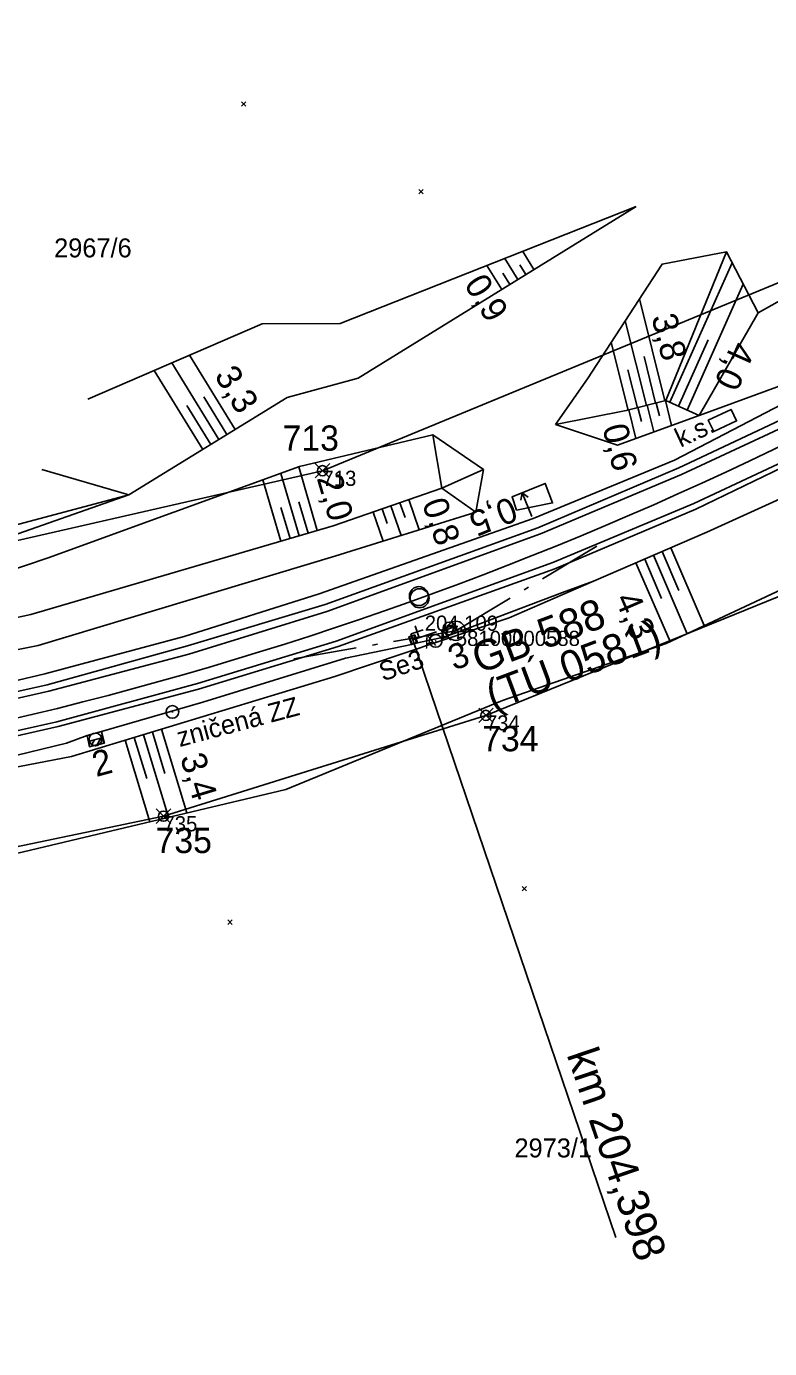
# Model space of a CAD drawing. Extents: x -800194 to -799078, y -1007177 to -1006597.
# Drawn here: x -799583.1 to -799524.3, y -1007037.9 to -1006933.3 of the extents above; entities that cross this region are included whole.
import ezdxf

# ---------------------------------------------------------------- set-up
doc = ezdxf.new("R2010")
doc.units = 0
for name, color, linetype in [('02_Osa_koleje', 7, 'Continuous'), ('_Vrstva 7 - Přesunutá', 7, 'Continuous'), ('Obvod stavby', 7, 'Continuous'), ('Vrstva 11', 7, 'Continuous'), ('Vrstva 12', 7, 'Continuous'), ('Vrstva 13', 7, 'Continuous'), ('Vrstva 25', 7, 'Continuous'), ('Vrstva 4', 7, 'Continuous'), ('Vrstva 48', 7, 'Continuous'), ('Vrstva 49', 7, 'Continuous'), ('Vrstva 50', 7, 'Continuous'), ('Vrstva 53', 7, 'Continuous'), ('Vrstva 55', 7, 'Continuous'), ('Vrstva 57', 7, 'Continuous'), ('Vrstva 6', 7, 'Continuous'), ('Vrstva 60', 7, 'Continuous'), ('Vrstva 61', 7, 'Continuous'), ('Vrstva 63', 7, 'Continuous'), ('Vrstva 7', 7, 'Continuous')]:
    doc.layers.add(name, color=color, linetype=linetype)

msp = doc.modelspace()

# ---------------------------------------------------------------- linework, layer by layer
at = {"layer": '02_Osa_koleje'}
msp.add_arc((-799651.02, -1006703.89), 292, 255.6249, 308.2052, dxfattribs=at)
at = {"layer": '_Vrstva 7 - Přesunutá'}
msp.add_circle((-799551.96, -1006978.57), 0.75, dxfattribs=at)
at = {"layer": 'Obvod stavby'}
for p, q in [((-799560.21, -1006969.05), (-799559.07, -1006967.91)), ((-799560.21, -1006967.91), (-799559.07, -1006969.05)), ((-799547.28, -1006988.4), (-799546.14, -1006987.26)), ((-799547.28, -1006987.26), (-799546.14, -1006988.4)), ((-799572.79, -1006996.37), (-799571.65, -1006995.23)), ((-799572.79, -1006995.23), (-799571.65, -1006996.37))]:
    msp.add_line(p, q, dxfattribs=at)
for points in [[(-799683.81, -1006990.52), (-799664.23, -1006992.09), (-799644.23, -1006992.31), (-799624.62, -1006991.18), (-799605.02, -1006988.7), (-799601.63, -1006988.13), (-799603.07, -1006978.39), (-799559.64, -1006968.48), (-799519.68, -1006952.01)], [(-799521.98, -1006977.8), (-799546.71, -1006987.83), (-799572.22, -1006995.8), (-799583.97, -1006998.26), (-799599.63, -1007001.65), (-799600.6, -1006995.06), (-799604.02, -1006995.63), (-799623.98, -1006998.15), (-799644.19, -1006999.31), (-799664.43, -1006999.09), (-799684.6, -1006997.48)]]:
    msp.add_lwpolyline(points, dxfattribs=at)
for centre in [(-799559.64, -1006968.48), (-799546.71, -1006987.83), (-799572.22, -1006995.8)]:
    msp.add_circle(centre, 0.4, dxfattribs=at)
at = {"layer": 'Vrstva 11'}
for p, q in [((-799549.13, -1006980.79), (-799550.08, -1006981.14)), ((-799549.87, -1006981.38), (-799549.69, -1006981)), ((-799549.49, -1006981.45), (-799549.2, -1006980.81)), ((-799577.11, -1006989.6), (-799578.08, -1006989.86)), ((-799577.53, -1006990.23), (-799577.18, -1006989.62)), ((-799577.9, -1006990.13), (-799577.69, -1006989.76))]:
    msp.add_line(p, q, dxfattribs=at)
for centre in [(-799549.6, -1006980.96), (-799577.6, -1006989.73)]:
    msp.add_circle(centre, 0.503, dxfattribs=at)
for centre, start, end in [((-799549.6, -1006980.96), 200.5311, 20.5311), ((-799577.6, -1006989.73), 194.9449, 14.9449)]:
    msp.add_arc(centre, 0.503, start, end, dxfattribs=at)
at = {"layer": 'Vrstva 12'}
for p, q in [((-799552.8, -1006981.61), (-799552.75, -1006981.62)), ((-799552.57, -1006982.18), (-799552.61, -1006982.23)), ((-799552.38, -1006981.51), (-799552.33, -1006981.46)), ((-799552.2, -1006982.07), (-799552.13, -1006982.09))]:
    msp.add_line(p, q, dxfattribs=at)
for points in [[(-799550.23, -1006981.08), (-799550.03, -1006981.64), (-799548.93, -1006981.25), (-799549.17, -1006980.59), (-799550.23, -1006981.08)], [(-799550.23, -1006981.08), (-799550.03, -1006981.64), (-799548.93, -1006981.25), (-799549.17, -1006980.59)], [(-799548.93, -1006981.25), (-799548.93, -1006981.25)], [(-799552.33, -1006981.46), (-799552.8, -1006981.61), (-799552.61, -1006982.23), (-799552.13, -1006982.09), (-799552.33, -1006981.46)], [(-799552.75, -1006981.62), (-799552.38, -1006981.51), (-799552.2, -1006982.07), (-799552.57, -1006982.18), (-799552.75, -1006981.62)], [(-799550.03, -1006981.64), (-799550.03, -1006981.64)], [(-799577.13, -1006989.11), (-799576.89, -1006990.02), (-799578.08, -1006990.31), (-799578.26, -1006989.41)], [(-799576.94, -1006990.02), (-799578.06, -1006990.29), (-799578.26, -1006989.41), (-799577.13, -1006989.11), (-799576.94, -1006990.02)], [(-799578.06, -1006990.29), (-799578.08, -1006990.31)], [(-799576.94, -1006990.02), (-799576.89, -1006990.02)]]:
    msp.add_lwpolyline(points, dxfattribs=at)
at = {"layer": 'Vrstva 13'}
for p, q in [((-799542.02, -1006969.49), (-799544.64, -1006970.55)), ((-799543.09, -1006972.09), (-799543.84, -1006970.23))]:
    msp.add_line(p, q, dxfattribs=at)
for points in [[(-799544.28, -1006971.59), (-799541.43, -1006971.03), (-799542.01, -1006969.49), (-799544.64, -1006970.55), (-799544.28, -1006971.59)], [(-799542.01, -1006969.49), (-799542.02, -1006969.49), (-799541.43, -1006971.03)], [(-799544.28, -1006971.59), (-799544.64, -1006970.55), (-799544.64, -1006970.55)], [(-799543.38, -1006970.58), (-799543.84, -1006970.23), (-799543.94, -1006970.81)]]:
    msp.add_lwpolyline(points, dxfattribs=at)
at = {"layer": 'Vrstva 25'}
msp.add_lwpolyline([(-799528.69, -1006965.38), (-799529.12, -1006964.48), (-799527.31, -1006963.63), (-799526.88, -1006964.54), (-799528.69, -1006965.38)], dxfattribs=at)
at = {"layer": 'Vrstva 4'}
for points in [[(-799766.32, -1006970.57), (-799760.95, -1006972.54), (-799747.64, -1006977.46), (-799730.55, -1006982.98), (-799710.07, -1006987.58), (-799704.73, -1006988.35), (-799693, -1006990.37), (-799682.43, -1006991.64), (-799671.27, -1006992.62), (-799659.31, -1006993.03), (-799648.69, -1006993.12), (-799637.4, -1006992.7), (-799625.91, -1006992.18), (-799614.96, -1006990.83), (-799603.91, -1006989.31), (-799592.73, -1006987.17), (-799581.6, -1006984.55), (-799570.58, -1006981.6), (-799559.91, -1006978.22), (-799542.96, -1006972.25), (-799531.79, -1006967.66), (-799521.29, -1006962.19), (-799511.24, -1006957.13)], [(-799779.68, -1006964.3), (-799766.32, -1006970.57), (-799761.25, -1006973.18), (-799747.77, -1006978.42), (-799730.77, -1006983.8), (-799710.33, -1006988.71), (-799704.92, -1006989.74), (-799693.13, -1006991.41), (-799682.58, -1006992.93), (-799671.33, -1006993.88), (-799659.36, -1006994.45), (-799648.66, -1006994.5), (-799637.23, -1006994.13), (-799626.07, -1006993.34), (-799614.79, -1006992.17), (-799603.67, -1006990.51), (-799592.47, -1006988.45), (-799581.28, -1006985.92), (-799570.22, -1006983), (-799559.3, -1006979.61), (-799542.38, -1006973.48), (-799531.24, -1006968.77), (-799520.48, -1006963.76), (-799510.39, -1006958.54)], [(-799776.86, -1006969.09), (-799770.96, -1006971.65), (-799761.91, -1006975.65), (-799748.54, -1006980.78), (-799731.46, -1006986.21), (-799711.13, -1006991.05), (-799705.48, -1006992.16), (-799693.53, -1006994.08), (-799682.8, -1006995.38), (-799671.51, -1006996.32), (-799659.45, -1006996.85), (-799648.59, -1006996.95), (-799637.26, -1006996.57), (-799625.83, -1006995.77), (-799614.55, -1006994.59), (-799603.2, -1006992.95), (-799591.97, -1006990.86), (-799580.65, -1006988.34), (-799569.53, -1006985.31), (-799558.56, -1006981.95), (-799541.41, -1006975.74), (-799530.26, -1006971.07), (-799519.46, -1006966), (-799509.25, -1006960.72)], [(-799776.86, -1006969.09), (-799771.26, -1006971.98), (-799762.13, -1006976.09), (-799748.71, -1006981.29), (-799731.51, -1006986.35), (-799711.22, -1006991.46), (-799705.53, -1006992.59), (-799693.58, -1006994.54), (-799682.85, -1006995.9), (-799671.5, -1006996.81), (-799659.56, -1006997.36), (-799648.62, -1006997.34), (-799637.28, -1006997.07), (-799625.83, -1006996.3), (-799614.43, -1006995.11), (-799603.18, -1006993.47), (-799591.85, -1006991.26), (-799580.56, -1006988.7), (-799569.45, -1006985.75), (-799558.39, -1006982.39), (-799541.27, -1006976.23), (-799530.1, -1006971.51), (-799519.4, -1006966.36), (-799509.09, -1006961.13)], [(-799779.01, -1006963.02), (-799770.63, -1006967.94), (-799766.32, -1006970.57), (-799761.02, -1006972.82), (-799747.75, -1006977.97), (-799730.72, -1006983.27), (-799710.2, -1006988.11), (-799704.77, -1006989.18), (-799693.07, -1006990.96), (-799682.55, -1006992.24), (-799671.27, -1006993.22), (-799659.39, -1006993.77), (-799648.66, -1006993.82), (-799637.39, -1006993.53), (-799625.77, -1006992.73), (-799614.9, -1006991.54), (-799603.91, -1006989.96), (-799592.57, -1006987.89), (-799581.42, -1006985.42), (-799570.33, -1006982.33), (-799559.43, -1006979.07), (-799542.6, -1006973.01), (-799531.45, -1006968.25), (-799520.74, -1006963.21)], [(-799683.1, -1006997.41), (-799671.67, -1006998.28), (-799659.52, -1006998.78), (-799648.52, -1006998.59), (-799637.01, -1006998.22), (-799625.7, -1006997.42), (-799614.69, -1006996.42), (-799603.02, -1006994.65), (-799591.63, -1006992.87), (-799579.9, -1006990.02), (-799578.26, -1006989.41), (-799577.13, -1006989.11), (-799569.11, -1006986.79), (-799557.83, -1006983.31), (-799552.61, -1006982.23), (-799552.13, -1006982.09), (-799550.03, -1006981.64), (-799548.93, -1006981.25), (-799540.64, -1006978.12), (-799538.19, -1006977.21), (-799529.22, -1006973.34), (-799517.86, -1006968.17)]]:
    msp.add_lwpolyline(points, dxfattribs=at)
at = {"layer": 'Vrstva 48'}
for p, q in [((-799544.18, -1006953.37), (-799545.21, -1006951.7)), ((-799542.91, -1006952.58), (-799543.8, -1006951.14)), ((-799532.16, -1006963.07), (-799527.23, -1006952.03)), ((-799545.46, -1006954.16), (-799546.63, -1006952.26)), ((-799544.82, -1006953.76), (-799545.37, -1006952.87)), ((-799543.54, -1006952.97), (-799544.03, -1006952.19)), ((-799530.79, -1006963.68), (-799526.35, -1006953.73)), ((-799532.55, -1006962.96), (-799534.57, -1006954.9)), ((-799534.01, -1006963.32), (-799535.68, -1006956.62)), ((-799531.48, -1006963.38), (-799529.13, -1006958.13)), ((-799566.56, -1006965.23), (-799570.17, -1006959.35)), ((-799535.46, -1006963.68), (-799536.8, -1006958.34)), ((-799567.84, -1006966.02), (-799571.56, -1006959.95)), ((-799533.28, -1006963.14), (-799534.2, -1006959.45)), ((-799569.11, -1006966.8), (-799572.95, -1006960.55)), ((-799534.73, -1006963.5), (-799535.49, -1006960.49)), ((-799568.48, -1006966.41), (-799570.36, -1006963.33)), ((-799567.2, -1006965.63), (-799569.03, -1006962.64)), ((-799534.69, -1006963.49), (-799534.41, -1006964.58)), ((-799533.96, -1006963.31), (-799533.43, -1006965.41)), ((-799533.23, -1006963.13), (-799532.98, -1006964.14)), ((-799532.5, -1006962.94), (-799532.02, -1006964.9)), ((-799535.41, -1006963.67), (-799534.85, -1006965.93)), ((-799561.49, -1006973.63), (-799562.94, -1006968.7)), ((-799560.05, -1006973.21), (-799561.52, -1006968.18)), ((-799562.93, -1006974.05), (-799564.35, -1006969.21)), ((-799552.81, -1006970.76), (-799551.98, -1006973.15)), ((-799562.21, -1006973.84), (-799562.93, -1006971.4)), ((-799560.77, -1006973.42), (-799561.5, -1006970.93)), ((-799555.64, -1006971.75), (-799554.84, -1006974.05)), ((-799554.93, -1006971.5), (-799554.53, -1006972.66)), ((-799554.23, -1006971.26), (-799553.41, -1006973.6)), ((-799553.52, -1006971.01), (-799553.11, -1006972.19)), ((-799532.77, -1006974.88), (-799531.44, -1006977.96)), ((-799532.08, -1006974.58), (-799529.43, -1006980.73)), ((-799534.84, -1006975.77), (-799532.14, -1006982)), ((-799534.15, -1006975.47), (-799532.81, -1006978.58)), ((-799533.46, -1006975.17), (-799530.78, -1006981.37)), ((-799574.53, -1006989.58), (-799573.54, -1006992.82)), ((-799573.81, -1006989.36), (-799571.83, -1006995.89)), ((-799573.09, -1006989.15), (-799572.1, -1006992.43)), ((-799572.38, -1006988.93), (-799570.37, -1006995.54)), ((-799575.25, -1006989.8), (-799573.29, -1006996.24))]:
    msp.add_line(p, q, dxfattribs=at)
at = {"layer": 'Vrstva 49'}
for p, q in [((-799566.06, -1006939.3), (-799565.71, -1006939.65)), ((-799566.06, -1006939.65), (-799565.71, -1006939.3)), ((-799552.02, -1006946.24), (-799551.67, -1006946.59)), ((-799552.02, -1006946.59), (-799551.67, -1006946.24)), ((-799525.18, -1006956), (-799529.84, -1006964.11)), ((-799550.2, -1006969.86), (-799546.89, -1006968.39)), ((-799550.2, -1006969.86), (-799547.5, -1006971.75)), ((-799543.85, -1007001.37), (-799543.5, -1007001.72)), ((-799543.85, -1007001.72), (-799543.5, -1007001.37)), ((-799567.13, -1007004.01), (-799566.78, -1007004.36)), ((-799567.13, -1007004.36), (-799566.78, -1007004.01))]:
    msp.add_line(p, q, dxfattribs=at)
for points in [[(-799581.84, -1006968.38), (-799574.95, -1006970.38), (-799562.43, -1006962.7), (-799556.81, -1006961.17), (-799534.83, -1006947.59)], [(-799534.83, -1006947.59), (-799558.24, -1006956.85), (-799564.4, -1006956.87), (-799578.21, -1006962.82)], [(-799510.22, -1006947.62), (-799525.18, -1006956), (-799527.68, -1006951.16), (-799532.77, -1006952.14), (-799538.67, -1006961.22), (-799541.2, -1006964.83)], [(-799541.2, -1006964.83), (-799535.61, -1006963.72), (-799532.47, -1006962.94), (-799527.68, -1006951.16)], [(-799532.47, -1006962.94), (-799529.84, -1006964.11), (-799521.84, -1006961.19), (-799512.05, -1006955.96)], [(-799710.32, -1006994.82), (-799708.87, -1006995.03), (-799692.77, -1006997.82), (-799673.3, -1007001.05), (-799659.56, -1007000.48), (-799648.46, -1007000.69), (-799625.45, -1006999.1), (-799615.7, -1006997.51), (-799614.57, -1006997.35), (-799602.96, -1006995.58), (-799579.5, -1006991.09), (-799558.66, -1006984.76), (-799544.86, -1006980.11), (-799538.19, -1006977.21), (-799529.22, -1006973.34), (-799517.86, -1006968.17), (-799516.56, -1006967), (-799515.53, -1006966.51), (-799507.82, -1006962.78)], [(-799541.2, -1006964.83), (-799536.29, -1006966.45), (-799529.84, -1006964.11)], [(-799621.79, -1006985.66), (-799603.52, -1006982.85), (-799581.35, -1006975.36), (-799561.47, -1006968.16), (-799550.92, -1006965.64), (-799546.89, -1006968.39)], [(-799619.91, -1006986.72), (-799603.2, -1006984.32), (-799582.71, -1006979.85), (-799558.8, -1006972.84), (-799550.2, -1006969.86), (-799550.92, -1006965.64)], [(-799621.79, -1006985.66), (-799621.59, -1006987.7), (-799603.12, -1006986.49), (-799582.14, -1006982.3), (-799558.67, -1006975.25), (-799547.5, -1006971.75), (-799546.89, -1006968.39)], [(-799641.81, -1007006.94), (-799621, -1007006.24), (-799608.68, -1007003.52), (-799602.42, -1007004.97), (-799584.29, -1006998.85), (-799562.54, -1006993.68), (-799545.4, -1006986.65), (-799532.46, -1006982.15), (-799507.06, -1006970.25)], [(-799574.95, -1006970.38), (-799603.15, -1006977.91), (-799621.41, -1006980.87), (-799634.22, -1006983.56), (-799639.94, -1006987.57)], [(-799639.94, -1006987.57), (-799633.79, -1006986.38), (-799621.45, -1006982.97), (-799603.21, -1006980.3), (-799574.95, -1006970.38)]]:
    msp.add_lwpolyline(points, dxfattribs=at)
at = {"layer": 'Vrstva 50'}
msp.add_line((-799571.56, -1006987.58), (-799571.46, -1006987.55), dxfattribs=at)
msp.add_circle((-799571.51, -1006987.56), 0.5, dxfattribs=at)
at = {"layer": 'Vrstva 53'}
for points in [[(-799686.25, -1006963.73), (-799670.17, -1006962.64), (-799668.03, -1006961.74), (-799668, -1006962.02), (-799667.43, -1006981.06), (-799637.16, -1006982.06), (-799603.07, -1006978.39), (-799559.64, -1006968.48), (-799519.68, -1006952.01)], [(-799521.98, -1006977.8), (-799546.71, -1006987.83), (-799572.22, -1006995.8), (-799583.97, -1006998.26), (-799599.63, -1007001.65), (-799584.37, -1007069.36), (-799591.04, -1007071.48), (-799597.25, -1007073.58), (-799607.27, -1007078.7), (-799623.27, -1007096.82), (-799619.94, -1007099.79), (-799606.31, -1007085.7), (-799604.36, -1007100.23), (-799602.09, -1007115.59), (-799604.31, -1007116.28), (-799613.8, -1007119.26), (-799629.52, -1007122.44), (-799580.26, -1007176.65)]]:
    msp.add_lwpolyline(points, dxfattribs=at)
at = {"layer": 'Vrstva 55'}
for points in [[(-799667.43, -1006981.06), (-799637.16, -1006982.06), (-799603.07, -1006978.39), (-799559.64, -1006968.48), (-799519.68, -1006952.01)], [(-799599.63, -1007001.65), (-799583.97, -1006998.26), (-799572.22, -1006995.8), (-799546.71, -1006987.83), (-799521.98, -1006977.8), (-799495.25, -1006963.74), (-799489.22, -1006959.79), (-799487.22, -1006958.47)]]:
    msp.add_lwpolyline(points, dxfattribs=at)
at = {"layer": 'Vrstva 6'}
for p, q in [((-799550.61, -1006981.22), (-799552.49, -1006981.86)), ((-799552.65, -1006981.39), (-799552.33, -1006982.33)), ((-799536.43, -1007029.12), (-799552.52, -1006981.78))]:
    msp.add_line(p, q, dxfattribs=at)
at = {"layer": 'Vrstva 60'}
for p, q in [((-799559.64, -1006968.48), (-799559.64, -1006968.48)), ((-799549.09, -1006981.14), (-799549.09, -1006981.14)), ((-799546.71, -1006987.83), (-799546.71, -1006987.83)), ((-799572.22, -1006995.8), (-799572.22, -1006995.8))]:
    msp.add_line(p, q, dxfattribs=at)
at = {"layer": 'Vrstva 63'}
for p, q in [((-799542.23, -1006977.03), (-799537.94, -1006974.46)), ((-799543.69, -1006977.9), (-799543.34, -1006977.69)), ((-799549.09, -1006981.14), (-799544.8, -1006978.57)), ((-799549.09, -1006981.14), (-799554.02, -1006981.99)), ((-799549.14, -1006981.15), (-799549.05, -1006981.12)), ((-799555.3, -1006982.21), (-799555.69, -1006982.28)), ((-799556.97, -1006982.5), (-799561.9, -1006983.36))]:
    msp.add_line(p, q, dxfattribs=at)
msp.add_circle((-799549.09, -1006981.14), 0.756, dxfattribs=at)
at = {"layer": 'Vrstva 7'}
for p, q in [((-799552.62, -1006981.39), (-799551.67, -1006981.07)), ((-799552.31, -1006980.76), (-799551.98, -1006981.7)), ((-799550.73, -1006981.95), (-799550.64, -1006981.92))]:
    msp.add_line(p, q, dxfattribs=at)
for centre, radius in [((-799552.01, -1006978.4), 0.75), ((-799550.69, -1006981.94), 0.5)]:
    msp.add_circle(centre, radius, dxfattribs=at)

# ---------------------------------------------------------------- texts
at = {"layer": 'Obvod stavby'}
for s, p in [('713', (-799562.8, -1006966.9)), ('734', (-799547.01, -1006990.67)), ('735', (-799572.85, -1006998.72))]:
    msp.add_text(s, height=2, rotation=360, dxfattribs=at).set_placement(p)
at = {"layer": 'Vrstva 11'}
for s, rotation, p in [('3', 20.5311, (-799549.23, -1006984.3)), ('2', 14.9449, (-799577.55, -1006992.71))]:
    msp.add_text(s, height=2, rotation=rotation, dxfattribs=at).set_placement(p)
at = {"layer": 'Vrstva 13'}
msp.add_text('0,5', height=2, rotation=202.0385, dxfattribs=at).set_placement((-799544.77, -1006970.49))
at = {"layer": 'Vrstva 25'}
msp.add_text('k.s.', height=1.5, rotation=25.0865, dxfattribs=at).set_placement((-799531.31, -1006966.67))
at = {"layer": 'Vrstva 48'}
for s, rotation, p in [('0,9', 301.724, (-799548.49, -1006953.74)), ('3,8', 284.0577, (-799533.63, -1006956.32)), ('4,0', 245.9384, (-799527.16, -1006958.11)), ('3,3', 301.5339, (-799568.24, -1006960.96)), ('0,6', 284.0577, (-799537.51, -1006965.05)), ('2,0', 286.3372, (-799560.11, -1006969.06)), ('0,8', 289.0997, (-799551.79, -1006971.05)), ('4,3', 293.3695, (-799536.54, -1006978.61)), ('3,4', 286.8948, (-799570.92, -1006991.15))]:
    msp.add_text(s, height=2, rotation=rotation, dxfattribs=at).set_placement(p)
at = {"layer": 'Vrstva 50'}
msp.add_text('zničená ZZ', height=1.5, rotation=14.9449, dxfattribs=at).set_placement((-799570.94, -1006990.34))
at = {"layer": 'Vrstva 57'}
for s, p in [('2967/6', (-799580.87, -1006951.61)), ('2973/1', (-799544.45, -1007022.79))]:
    msp.add_text(s, height=1.5, dxfattribs=at).set_placement(p)
at = {"layer": 'Vrstva 6'}
for s, height, rotation, p in [('  A A ', 1, 18.7608, (-799552.17, -1006982.81)), ('Se3', 1.5, 18.7608, (-799554.86, -1006985.15)), ('km 204,398', 2.5, 288.7608, (-799540.34, -1007014.64))]:
    msp.add_text(s, height=height, rotation=rotation, dxfattribs=at).set_placement(p)
at = {"layer": 'Vrstva 60'}
for s, p in [('713', (-799559.64, -1006969.68)), ('58100000588', (-799549.09, -1006982.34)), ('734', (-799546.71, -1006989.03)), ('735', (-799572.22, -1006997))]:
    msp.add_text(s, height=1.2, dxfattribs=at).set_placement(p)
at = {"layer": 'Vrstva 61'}
msp.add_text('204.109', height=1.2, dxfattribs=at).set_placement((-799551.55, -1006981.14))
at = {"layer": 'Vrstva 63'}
for s, p in [('GB 588', (-799547.24, -1006984.56)), ('(TÚ 0581)', (-799546.15, -1006987.47))]:
    msp.add_text(s, height=2.4, rotation=20.5311, dxfattribs=at).set_placement(p)

doc.saveas('drawing.dxf')
